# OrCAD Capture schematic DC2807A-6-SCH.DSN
size Custom; company: ANALOG DEVICES; note: DEMO BOARD BILL OF MATERIALS; note: LIDAR RECEIVER
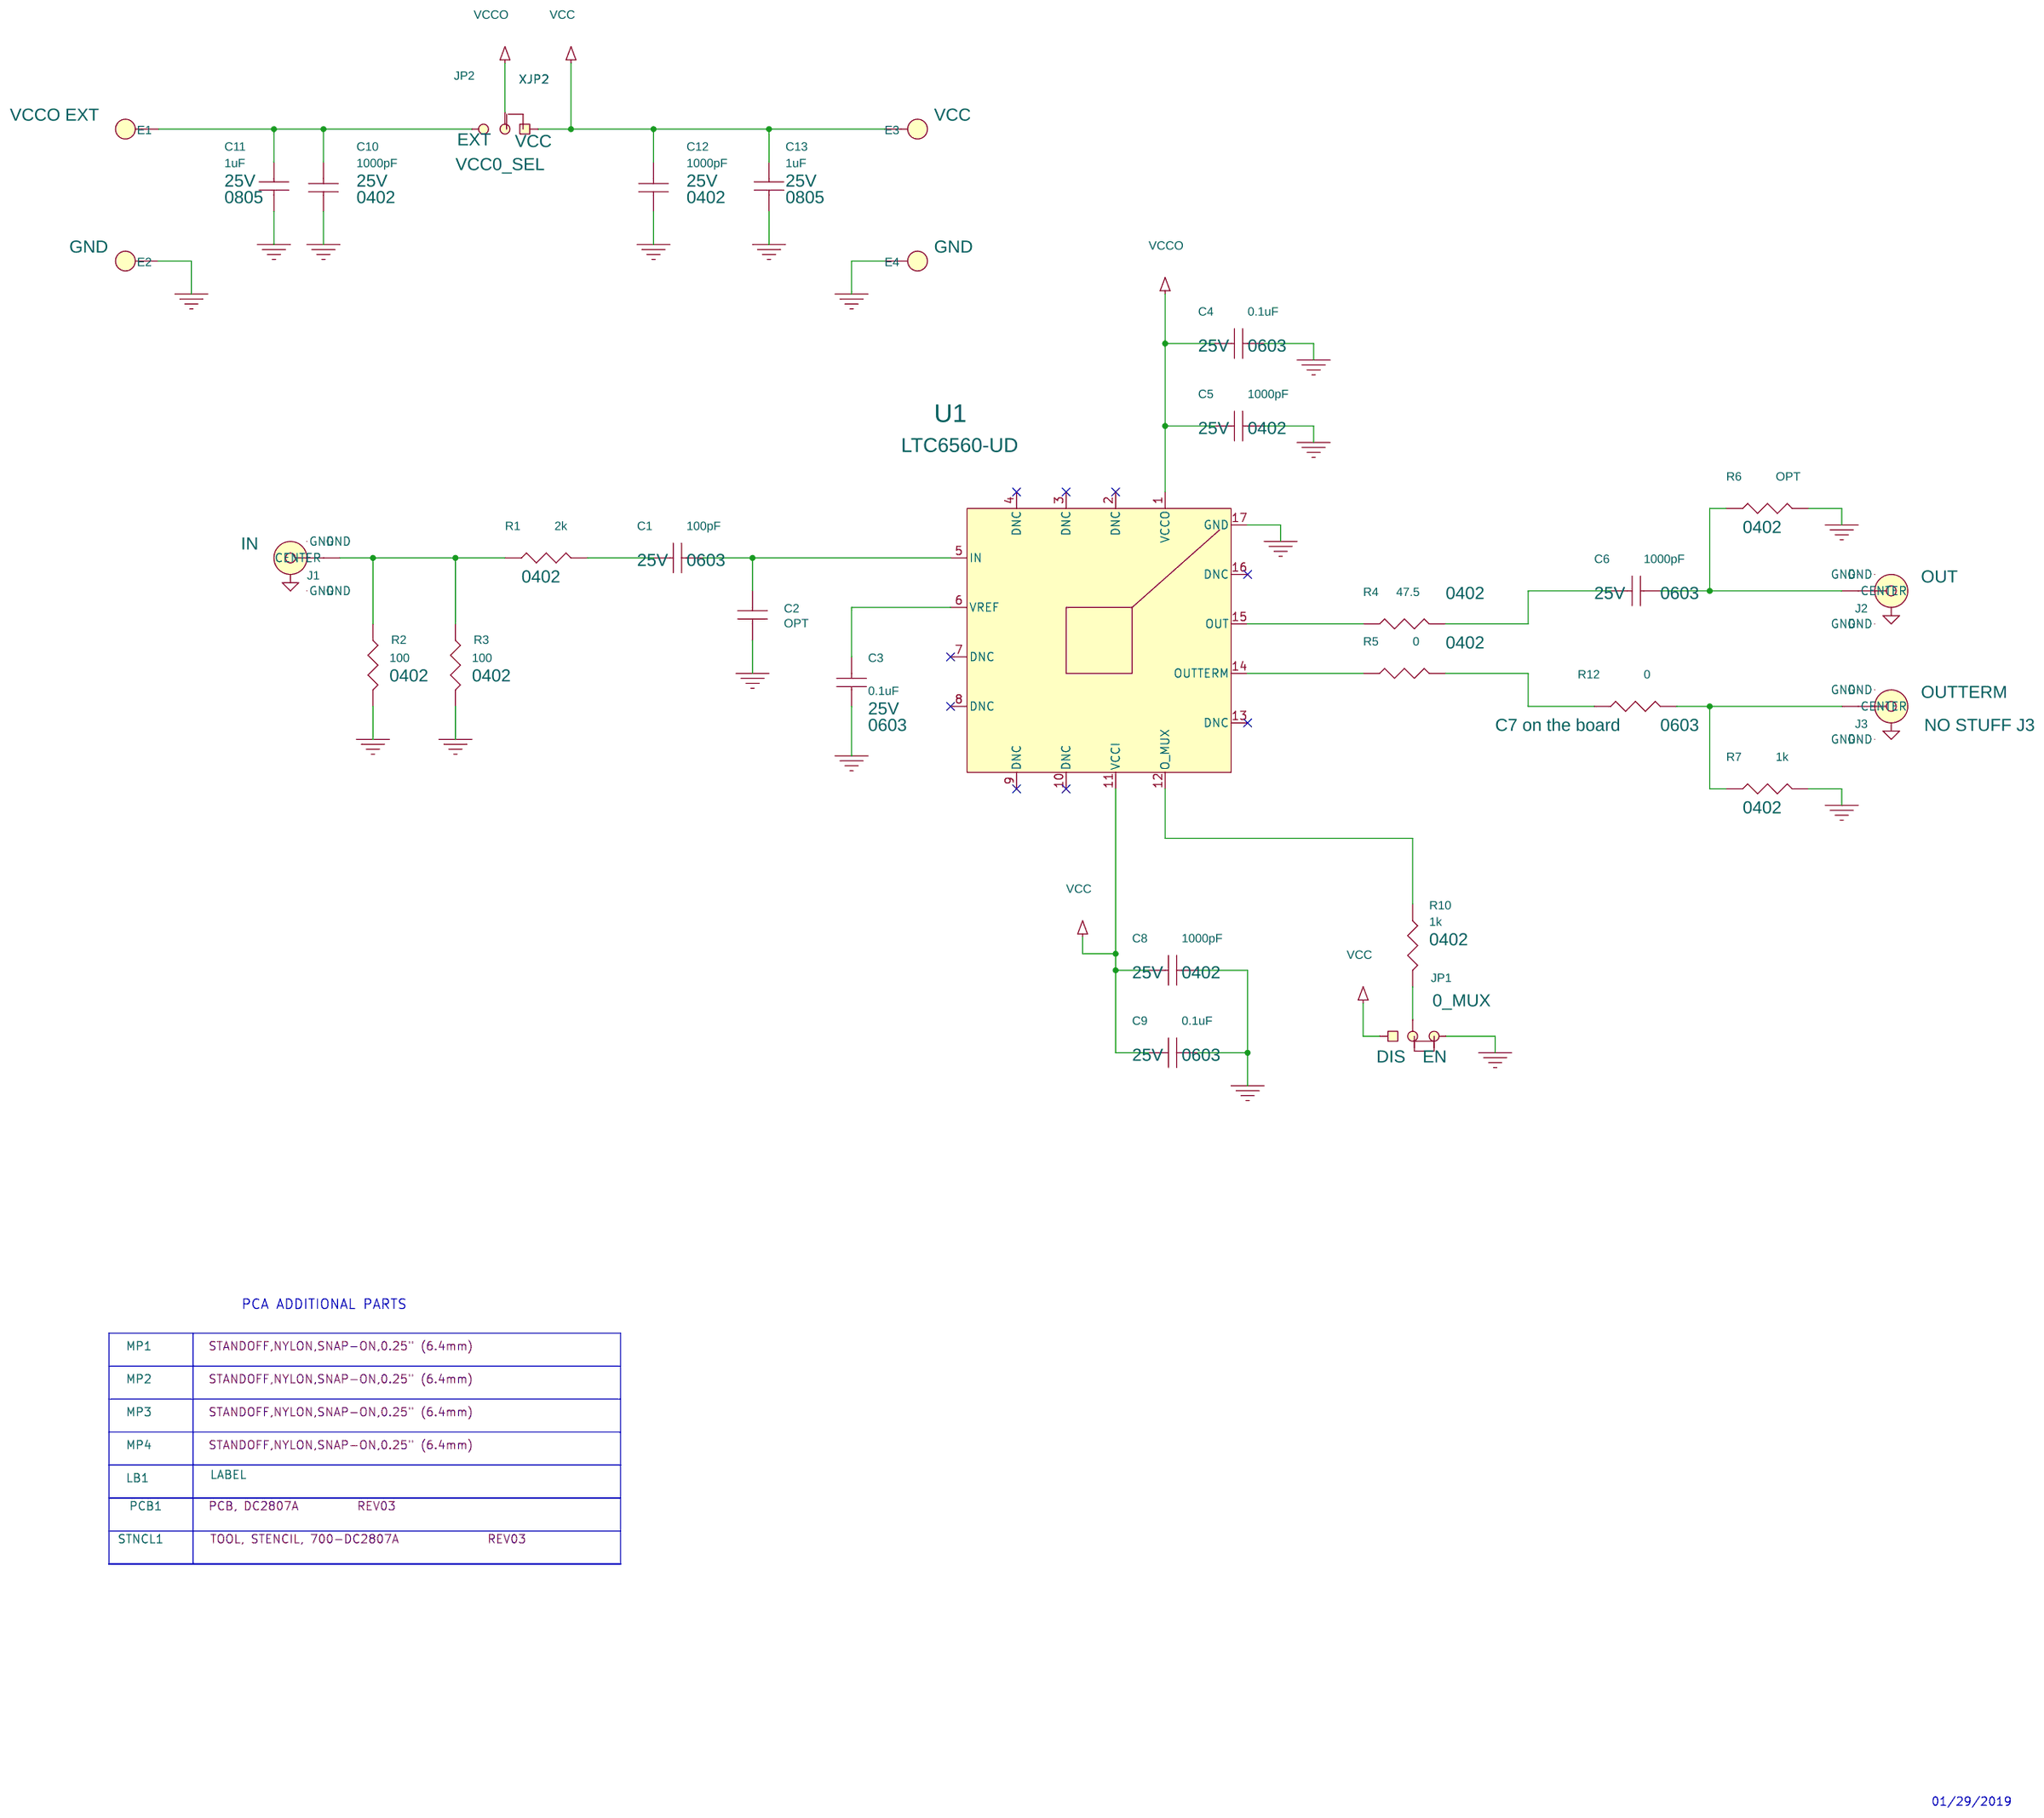
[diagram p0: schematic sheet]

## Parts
C1  100pF  [CC0603N]
C2  OPT  [CC0402N]
C3  0.1uF  [CC0603N]
C4  0.1uF  [CC0603N]
C5  1000pF  [CC0402N]
C6  1000pF  [CC0603N]
C8  1000pF  [CC0402N]
C9  0.1uF  [CC0603N]
C10  1000pF  [CC0402N]
C11  1uF  [CC0805N]
C12  1000pF  [CC0402N]
C13  1uF  [CC0805N]
E1  TEST POINT  [MILLMAX2308]
E2  TEST POINT  [MILLMAX2308]
E3  TEST POINT  [MILLMAX2308]
E4  TEST POINT  [MILLMAX2308]
J1  SMA  [EMERSON_142-0701-851]
J2  SMA  [EMERSON_142-0701-851]
J3  SMA  [EMERSON_142-0701-851]
JP1  HDR  [HD1X3-079]
JP2  HDR  [HD1X3-079]
LB1  LABEL  [895-0154_REV01]
MP1  STANDOFF  [MTG-8831]
MP2  STANDOFF  [MTG-8831]
MP3  STANDOFF  [MTG-8831]
MP4  STANDOFF  [MTG-8831]
PCB1  PCB, DC2807A
R1  2k  [CR0402N]
R2  100  [CR0402N]
R3  100  [CR0402N]
R4  47.5  [CR0402N]
R5  0  [CR0402N]
R6  OPT  [CR0402N]
R7  1k  [CR0402N]
R10  1k  [CR0402N]
R12  0  [CR0603N]
STNCL1  TOOL, STENCIL, 700-DC2807A
U1  LTC6560-UD  [LTC-UD-16-1700(AA)]
XJP1  SHUNT
XJP2  JUMPER LINK  [PCBJUMPER_2POS]

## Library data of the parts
C1 = CAP: CAP.,100pF,C0G,25V,10%,0603; CLASS: DISCRETE; Dielectric Type: C0G; FPLIST: CC0603N,CC0603L,CC0603M; Inventory Qty: 33000; Manufacturer: AVX; Manufacturer PN: 06033A101KAT2A; PART_NUMBER: 150-3276; Package Size: 0603; Rated Voltage: 25V; Tolerance: 10%
C2 = CAP: CAP., OPTION, 0402; CLASS: DISCRETE; FPLIST: CC0402N,CC0402L,CC0402M; PART_NUMBER: 150-3148; Package Size: 0402; Package Type: SMD
C3 C4 C9 = CAP: CAP.,0.1uF,X7R,25V,10%,0603; CLASS: DISCRETE; Dielectric Type: X7R; FPLIST: CC0603N,CC0603L,CC0603M; Inventory Qty: 41886; Manufacturer: AVX; Manufacturer PN: 06033C104KAT2A; PART_NUMBER: 150-0065; Package Size: 0603; Rated Voltage: 25V; Tolerance: 10%
C5 C8 C10 C12 = CAP: CAP.,1000pF,X7R,25V,10%,0402; CLASS: DISCRETE; Dielectric Type: X7R; FPLIST: CC0402N,CC0402L,CC0402M; Inventory Qty: 28890; Manufacturer: AVX; Manufacturer PN: 04023C102KAT2A; PART_NUMBER: 150-2012; Package Size: 0402; Rated Voltage: 25V; Tolerance: 10%
C6 = CAP: CAP.,1000pF,C0G,25V,10%,0603; CLASS: DISCRETE; Dielectric Type: C0G; FPLIST: CC0603N,CC0603L,CC0603M; Inventory Qty: 33000; Manufacturer: AVX; Manufacturer PN: 06033A102KAT2A; PART_NUMBER: 150-3278; Package Size: 0603; Rated Voltage: 25V; Tolerance: 10%
C11 C13 = CAP: CAP.,1uF,X7R,25V,10%,0805; CLASS: DISCRETE; Dielectric Type: X7R; FPLIST: CC0805N,CC0805L,CC0805M; Inventory Qty: 14558; Manufacturer: AVX; Manufacturer PN: 08053C105KAT2A; PART_NUMBER: 150-3037; Package Size: 0805; Rated Voltage: 25V; Tolerance: 10%
E1 = TEST_POINT_.156_MILL-MAX_2308: TEST POINT,TURRET,0.064" MTG. HOLE,PCB 0.062" THICK; 1: VCCO EXT; CLASS: IO; Inventory Qty: 841868; Manufacturer: MILL-MAX; Manufacturer PN: 2308-2-00-80-00-00-07-0; PART_NUMBER: 260-0004
E2 E4 = TEST_POINT_.156_MILL-MAX_2308: TEST POINT,TURRET,0.064" MTG. HOLE,PCB 0.062" THICK; 1: GND; CLASS: IO; Inventory Qty: 841868; Manufacturer: MILL-MAX; Manufacturer PN: 2308-2-00-80-00-00-07-0; PART_NUMBER: 260-0004
E3 = TEST_POINT_.156_MILL-MAX_2308: TEST POINT,TURRET,0.064" MTG. HOLE,PCB 0.062" THICK; 1: VCC; CLASS: IO; Inventory Qty: 841868; Manufacturer: MILL-MAX; Manufacturer PN: 2308-2-00-80-00-00-07-0; PART_NUMBER: 260-0004
J1 = CONN_SMA_5PIN: CONN.,SMA,JACK, RCPT,END LAUNCH, STR,50 OHMS; 1: IN; BOM Notes: NO STUFF J3; CLASS: IO; FPLIST: EMERSON_142-0701-851,SMA-CINCH-142-0761-881_142-0701-851; Inventory Qty: 26456; Manufacturer: CINCH/ BEL; Manufacturer PN: 142-0701-851; PART_NUMBER: 250-0446
J2 = CONN_SMA_5PIN: CONN.,SMA,JACK, RCPT,END LAUNCH, STR,50 OHMS; 1: OUT; BOM Notes: NO STUFF J3; CLASS: IO; FPLIST: EMERSON_142-0701-851,SMA-CINCH-142-0761-881_142-0701-851; Inventory Qty: 26456; Manufacturer: CINCH/ BEL; Manufacturer PN: 142-0701-851; PART_NUMBER: 250-0446
J3 = CONN_SMA_5PIN: CONN.,SMA,JACK, RCPT,END LAUNCH, STR,50 OHMS; 1: OUTTERM; BOM Notes: NO STUFF J3; CLASS: IO; FPLIST: EMERSON_142-0701-851,SMA-CINCH-142-0761-881_142-0701-851; Inventory Qty: 26456; Manufacturer: CINCH/ BEL; Manufacturer PN: 142-0701-851; PART_NUMBER: 250-0446
JP1 = 1X3_D: CONN.,HDR,MALE,1x3,2mm,STR, THT,NO SUBS. ALLOWED; 1: 0_MUX; 2: DIS; 3: EN; BOM Notes: NO STUFF JP2; CLASS: IO; Inventory Qty: 2469; Manufacturer: Wurth Elektronik; Manufacturer PN: 62000311121; PART_NUMBER: 250-0639
JP2 = 1X3_D: CONN.,HDR,MALE,1x3,2mm,STR, THT,NO SUBS. ALLOWED; 1: VCC0_SEL; 2: VCC; 3: EXT; BOM Notes: NO STUFF JP2; CLASS: IO; Inventory Qty: 2469; Manufacturer: Wurth Elektronik; Manufacturer PN: 62000311121; PART_NUMBER: 250-0639
LB1 = BLANK_LABEL: LABEL SPEC, DEMO BOARD SERIAL NUMBER; Inventory Qty: 0; Manufacturer: BRADY; Manufacturer PN: THT-96-717-10; PART_NUMBER: 895-0154
MP1-MP4 = BLANK_MECHANICAL_PART: STANDOFF,NYLON,SNAP-ON,0.25" (6.4mm); CLASS: MECHANICAL PART; Inventory Qty: 188176; Manufacturer: KEYSTONE; Manufacturer PN: 8831; PART_NUMBER: 763-0006
PCB1 = BLANK_PCB_PART: BOM Notes: REV03; CLASS: DISCRETE; Inventory Qty: 0; Manufacturer: EAGLE TECH. INC.; Manufacturer PN: 600-DC2807A; PART_NUMBER: 600-DC2807A
R1 = RES: RES.,2k OHMS,1%,1/16W,0402,AEC-Q200; CLASS: DISCRETE; FPLIST: CR0402N,CR0402L,CR0402M; Inventory Qty: 34486; Manufacturer: VISHAY; Manufacturer PN: CRCW04022K00FKED; PART_NUMBER: 100-0018; Package Size: 0402; Rated Power: 1/16W; Temperature Coefficient: 100ppm/C; Tolerance: 1%
R2 R3 = RES: RES.,100 OHMS,1%,1/16W,0402; CLASS: DISCRETE; FPLIST: CR0402N,CR0402L,CR0402M; Inventory Qty: 48112; Manufacturer: NIC; Manufacturer PN: NRC04F1000TRF; PART_NUMBER: 100-2626; Package Size: 0402; Rated Power: 1/16W; Temperature Coefficient: 100ppm/C; Tolerance: 1%
R4 = RES: RES.,47.5 OHMS,1%,1/16W,0402,AEC-Q200; CLASS: DISCRETE; Inventory Qty: 16621; Manufacturer: STACKPOLE ELECTRONICS; Manufacturer PN: RMCF0402FT47R5; PART_NUMBER: 100-1002; Package Size: 0402; Rated Power: 1/16W; Temperature Coefficient: 100ppm; Tolerance: 1%
R5 = RES: RES.,0 OHM,1/16W,0402; CLASS: DISCRETE; FPLIST: CR0402N,CR0402L,CR0402M; Inventory Qty: 188771; Manufacturer: ROHM; Manufacturer PN: MCR01MZPJ000; PART_NUMBER: 100-0215; Package Size: 0402; Rated Power: 1/16W
R6 = RES: RES., OPTION, 0402; CLASS: DISCRETE; FPLIST: CR0402N,CR0402L,CR0402M; PART_NUMBER: 100-0357; Package Size: 0402
R7 R10 = RES: RES.,1k OHMS,1%,1/16W,0402; CLASS: DISCRETE; FPLIST: CR0402N,CR0402L,CR0402M; Inventory Qty: 40501; Manufacturer: NIC; Manufacturer PN: NRC04F1001TRF; PART_NUMBER: 100-2861; Package Size: 0402; Rated Power: 1/16W; Temperature Coefficient: +/-100ppm; Tolerance: 1%
R12 = RES: RES.,0 OHM,1/10W,0603; 1: C7 on the board; BOM Notes: R12 IS LABELED C7 ON PCB; CLASS: DISCRETE; FPLIST: CR0603N,CR0603L,CR0603M; Inventory Qty: 33880; Manufacturer: BOURNS; Manufacturer PN: CR0603-J/-000ELF; PART_NUMBER: 100-2621; Package Size: 0603; Rated Power: 1/10W
STNCL1 = BLANK_STENCIL_PART: BOM Notes: REV03; CLASS: DISCRETE; Inventory Qty: 0; Manufacturer: LINEAR TECH.; Manufacturer PN: 830-DC2807A; PART_NUMBER: 830-DC2807A
U1 = LTC6560-UD: IC,Sgl Channel Transimpedance Amp,QFN-16 (3x3); CLASS: IC; Inventory Qty: 0; Manufacturer: LINEAR TECH.; Manufacturer PN: LTC6560IUD#PBF; PART_NUMBER: LTC6560IUD#PBF; Package Type: QFN-16 (3x3)
XJP1 = SHUNT_2MM_B: CONN.,SHUNT,FEMALE,2 POS,2mm; CLASS: IO; Inventory Qty: 31935; Manufacturer: Wurth Elektronik; Manufacturer PN: 60800213421; PART_NUMBER: 250-0485
XJP2 = SHNT_A: CONN.,JUMPER LINK,MALE,1x2,2.54mm,THT,WHITE INSULATED; CLASS: IO; Inventory Qty: 3780; Manufacturer: SAMTEC; Manufacturer PN: JL-100-25-T; PART_NUMBER: 250-0448

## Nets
GND: C2.2 C3.1 C4.2 C5.2 C8.2 C9.2 C10.1 C11.2 C12.1 C13.2 E2.1(A) E4.1(A) J1.2(GND) J1.3(GND) J1.4(GND) J1.5(GND) J2.2(GND) J2.3(GND) J2.4(GND) J2.5(GND) J3.2(GND) J3.3(GND) J3.4(GND) J3.5(GND) JP1.3 R2.2 R3.2 R6.2 R7.2 U1.17(GND)
VCC: C8.1 C9.1 C12.2 C13.1 E3.1(A) JP1.1 JP2.1 U1.11(VCCI)
VCCO: C4.1 C5.1 JP2.2 U1.1(VCCO)
N17285678: C10.2 C11.1 E1.1(A) JP2.3
N17289781: J1.1(CENTER) R1.1 R2.1 R3.1
N17289807: C1.1 R1.2
N17289809: C1.2 C2.1 U1.5(IN)
N17289839: C3.2 U1.6(VREF)
N17290262: R4.1 U1.15(OUT)
N17290272: R5.1 U1.14(OUTTERM)
N17290276: R5.2 R12.2
N17290278: C6.1 J2.1(CENTER) R6.1
N17290286: J3.1(CENTER) R7.1 R12.1
N17290310: C6.2 R4.2
N17290564: JP1.2 R10.2
N17290584: R10.1 U1.12(O_MUX)

Not connected (* = marked no-connect by the designer): U1 2(DNC)* 3(DNC)* 4(DNC)* 7(DNC)* 8(DNC)* 9(DNC)* 10(DNC)* 13(DNC)* 16(DNC)*

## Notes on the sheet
- PCA ADDITIONAL PARTS
- 01/29/2019
